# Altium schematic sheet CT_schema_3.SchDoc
size 283 x 147 mm
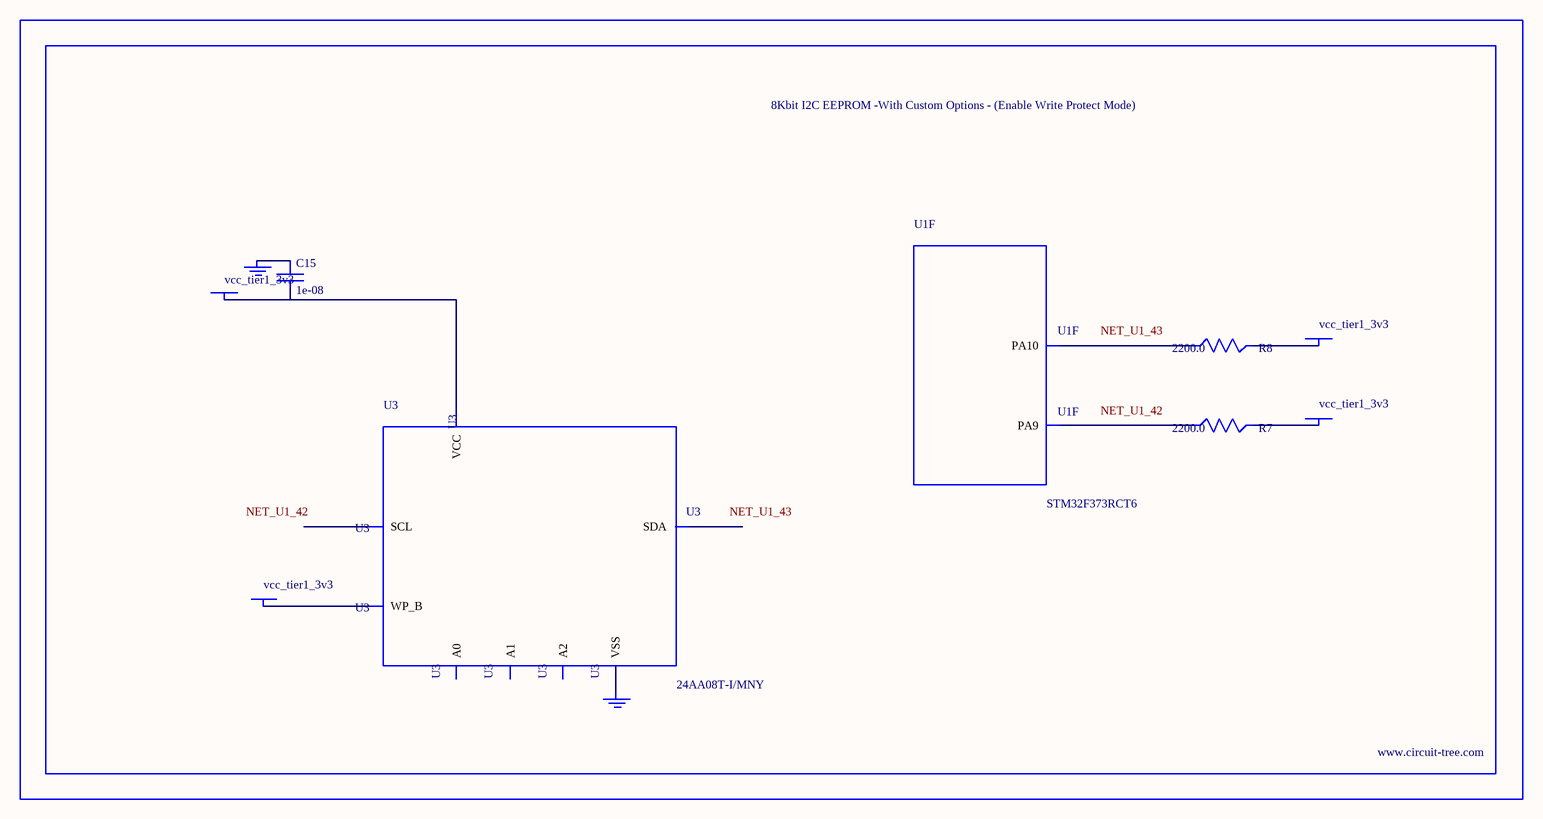
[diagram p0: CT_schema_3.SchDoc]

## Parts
BORDER2  (no value)
C15  1e-08  [C0402]
GND_INSTANCE_2_0  (no value)
GND_INSTANCE_2_1  (no value)
POWER_INSTANCE_2_0  vcc_tier1_3v3
POWER_INSTANCE_2_1  vcc_tier1_3v3
POWER_INSTANCE_2_2  vcc_tier1_3v3
POWER_INSTANCE_2_3  vcc_tier1_3v3
R7  2200.0  [R0603]
R8  2200.0  [R0603]
U1  STM32F373RCT6  [LQFP64]  (part F of 8)
U3  24AA08T-I/MNY  [TDFN-8/6MM]

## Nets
NetC15_1: C15.1 GND_INSTANCE_2_0.0(GND)
NetC15_2: C15.2 POWER_INSTANCE_2_1.0(PWR) U3.8(VCC)
NetGND_INSTANCE_2_1_0: GND_INSTANCE_2_1.0(GND) U3.4(VSS)
NetPOWER_INSTANCE_2_0_0: POWER_INSTANCE_2_0.0(PWR) U3.7(WP_B)
NetPOWER_INSTANCE_2_2_0: POWER_INSTANCE_2_2.0(PWR) R7.2
NetPOWER_INSTANCE_2_3_0: POWER_INSTANCE_2_3.0(PWR) R8.2
NetR7_1: R7.1 U1.42(PA9)
NetR8_1: R8.1 U1.43(PA10)

Not connected (* = marked no-connect by the designer): U3 1(A0) 2(A1) 3(A2) 5(SDA) 6(SCL)

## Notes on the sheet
- Labels drawn without touching a wire or pin: NET_U1_42, NET_U1_43

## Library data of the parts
BORDER2 = BORDER_PAGE2
C15 = C0402C103K3RAC
GND_INSTANCE_2_0 GND_INSTANCE_2_1 = GND
POWER_INSTANCE_2_0-POWER_INSTANCE_2_3 = PWR
R7 R8 = RC0603JR-072K2L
